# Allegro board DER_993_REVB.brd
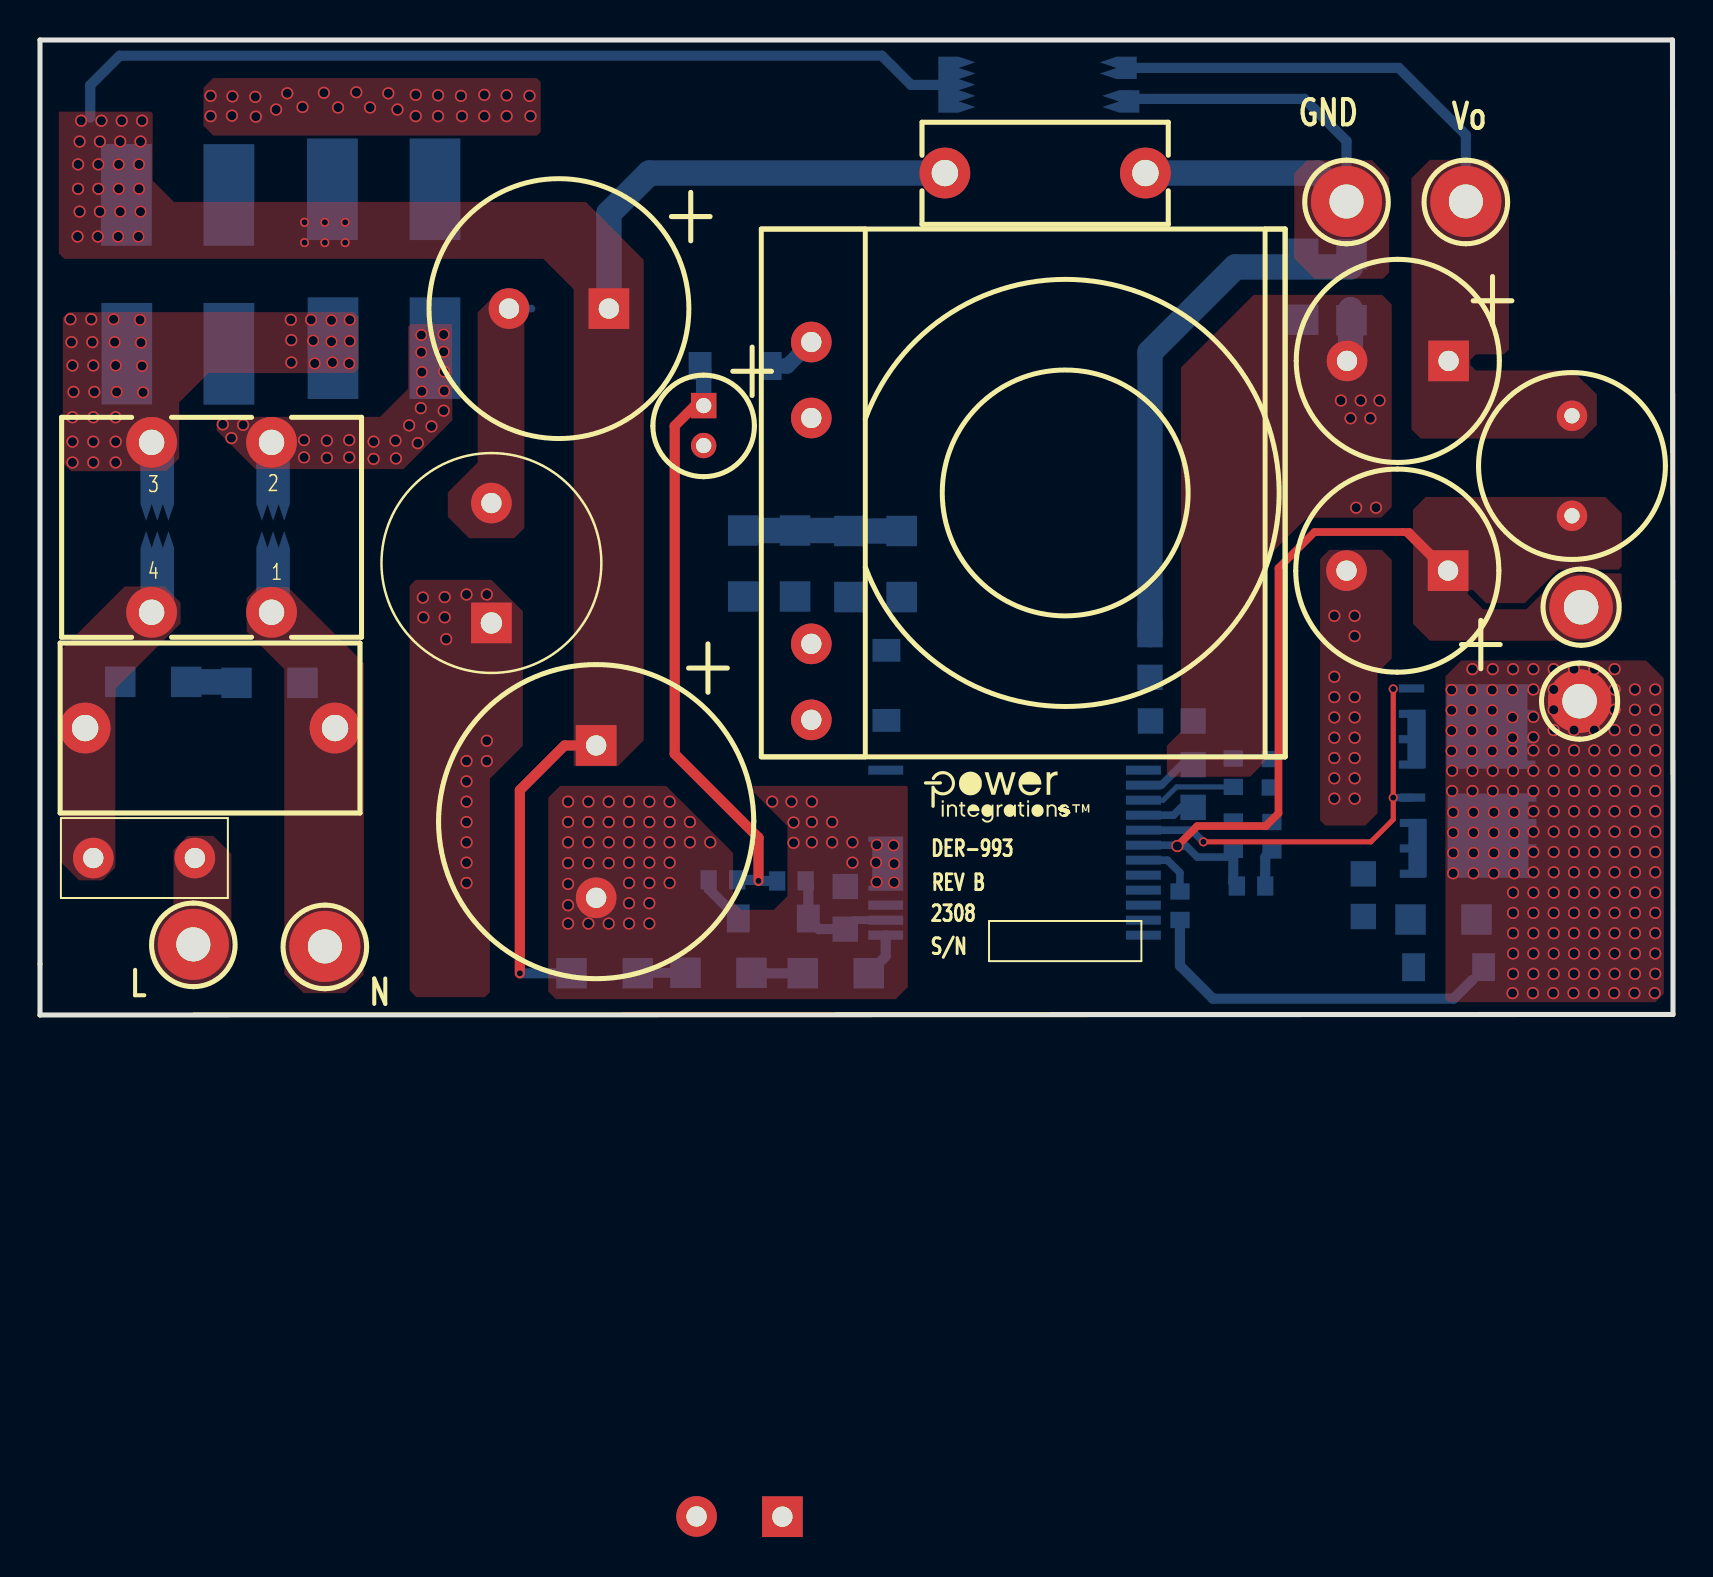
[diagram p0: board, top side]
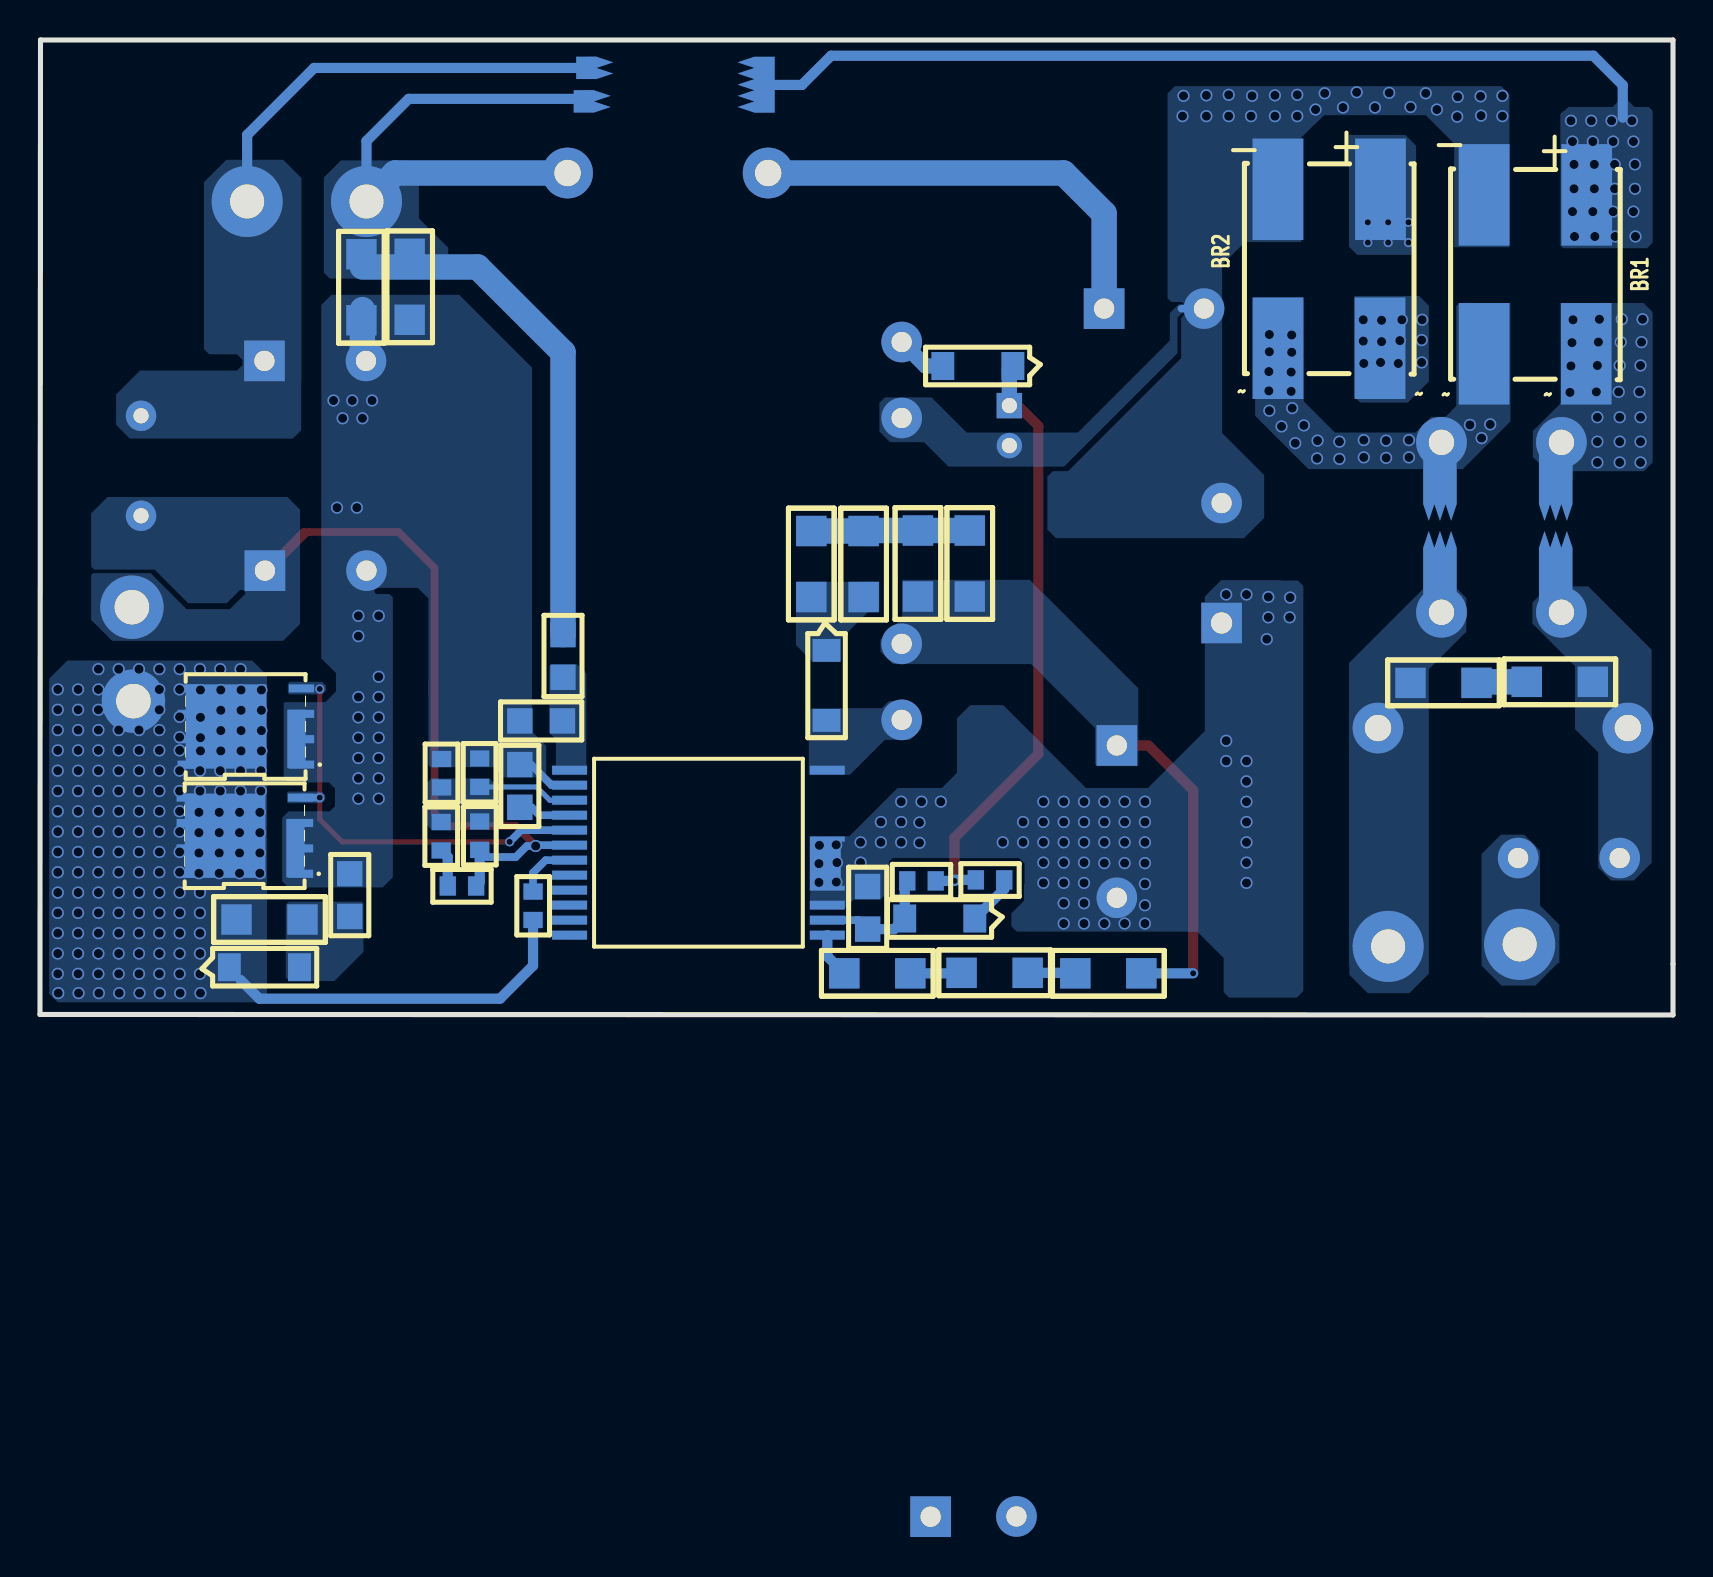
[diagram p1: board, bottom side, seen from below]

Outline 81.69 x 48.77 mm; copper layers: TOP, BOTTOM. Coordinates in mm from the lower left corner of the outline.
Outline path: 0,48.77 81.66,48.77 81.69,0.03 0,0 0,48.77

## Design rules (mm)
constraint set DEFAULT: min track width 0.203

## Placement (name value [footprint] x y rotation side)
BR1  Z4DGP408L-HF  [PI_SM_D_Z4D]  4.34 41.07 180 bottom
BR2  Z4DGP408L-HF  [PI_SM_D_Z4D]  14.66 41.35 180 bottom
C1  68 uF  [PIPOLCAPCLYD13MMD040]  25.96 35.33 180 top
C2  82 uF  [PIPOLCAPCLYD630LS300040]  27.82 13.48 270 top
C4  1 nF  [PISMC1206]  37.77 20.93 90 bottom
C5  22  uF  [PIPOLCAPCLYD200LS80030]  33.2 30.48 270 top
C6  4.7 uF  [PISMC0805]  40.28 4.29 90 bottom
C7  1.5 nF  [PISMC0805]  66.19 7.06 270 bottom
C8  2.2 uF  [PISMC0805]  57.68 12.52 270 bottom
C9  330 pF  [PISMC0603]  59.69 12.83 270 bottom
C10  4.7 uF  [PISMC0805]  57.68 14.71 180 bottom
C11  2.2 nF  [PISMC0603]  61.62 8.23 90 bottom
C12  820 uF  [PIPOLCAPCYLD400LS200040]  70.43 22.23 180 top
C13  820 uF  [PIPOLCAPCYLD400LS200040]  70.46 32.72 180 top
CX1  330 nF  [PINP_XCAPRAD15X8P5X14HD040]  14.76 14.35 180 top
CY1  2.2 nF  [PI_NP475X200LS395D040]  45.26 42.11 0 top
D1  S1MLHRVG  [PI_SM_SOD-123_12]  42.34 18.24 270 bottom
D2  S1MLHRVG  [PI_SM_SOD-123_12]  33.02 32.46 0 bottom
D3  UFM13PL-TP  [PI_SM_SOD-123_12]  72.21 2.39 180 bottom
F1  3.15 A  [PI_RST_MICROFUSE]  7.75 7.85 180 top
FL1  Hole_70mils  [PI_HOLE_70MIL]  77.09 20.37 0 top
FL2  Hole_70mils  [PI_HOLE_70MIL]  77.01 15.67 0 top
L1  18mH  [PI_CMC_18MH_SUMIDASF]  11.58 20.14 180 top
L2  12 uH  [PI_CHOKE_COILCRAFT_RFB1010]  22.58 22.61 90 top
L3  1 uH  [PI_CHOKE_D354LS197D030]  76.63 24.97 90 top
NOREF  -  []  89.79 -219.94 0 top
NOREF#2  -  []  43.66 12.09 0 top
NOREF#3  -  []  0.03 0.03 90 top
NOREF#4  -  []  -329.18 -232.92 0 top
NOREF#5  -  []  0 48.77 0 top
Q3  SIR170DP  [PISMPQFN5X6B]  68.66 7.06 90 bottom
Q4  SIR170DP  [PISMPQFN5X6B]  68.61 12.52 90 bottom
R1  2 M  [PISMR1206]  7.32 16.66 180 bottom
R2  2 M  [PISMR1206]  13.13 16.61 180 bottom
R3  470 k  [PISMR1206]  35.18 20.93 90 bottom
R4  20  [PISMR1206]  40.49 20.9 90 bottom
R5  20  [PISMR1206]  43.1 20.9 90 bottom
R6  11 k  [PISMR0603]  36.88 6.71 0 bottom
R7  100  [PISMR0603]  34.87 6.76 180 bottom
R8  47  [PISMR0603]  57.02 4.75 90 bottom
R9  10  [PISMR1206]  68.55 4.78 0 bottom
R13  0.011  [PISMR1206]  65.61 34.75 90 bottom
R14  10  [PISMR0805]  55.52 19.02 270 bottom
R15  100 k  [PISMR0603]  59.69 8.25 90 bottom
R16  3.92 k  [PISMR0603]  59.87 6.45 0 bottom
R17  11.8 k  [PISMR0603]  61.59 12.8 270 bottom
R18  1.00 M  [PISMR1206]  38.15 2.08 0 bottom
R19  1.20 M  [PISMR1206]  32.28 2.11 0 bottom
R20  1.20 M  [PISMR1206]  26.59 2.08 0 bottom
R21  0.011  [PISMR1206]  63.2 34.77 90 bottom
T1  PQ-2628  [PI_BOBBIN_PQ-2628_6P]  51.28 26.11 0 top
TP1  Line  [PITPKEYSTONE125X125]  7.67 3.53 0 top
TP2  Neutral  [PITPKEYSTONE125X125]  14.25 3.43 0 top
TP3  RED  [PITPKEYSTONE125X125]  71.32 40.69 0 top
TP4  BLK  [PITPKEYSTONE125X125]  65.35 40.69 0 top
U1  INN4275C-Hxxx  [PI_IC_INSOP_24D_IPC]  55.19 12.24 180 bottom
ZD1  MMSZ5247BT1G  [PI_SM_SOD-123_12]  34.92 4.83 0 bottom

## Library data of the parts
BR1 BR2 = DISCRETE BRIDGE_+~~-
C1 = CAP POL: alternate symbols: (pipolcapclyd13x30mmd040H)
C2 = CAP POL: alternate symbols: (pi_polcap_630ls300d40x1319_h)
C4 C6 C7 C10 C11 CY1 = CAP NP
C5 = CAP POL: alternate symbols: (pipolcapclyd200ls80030h)
C8 = CAP NP_0
C9 = CAP NP: alternate symbols: (pismc0603_1)
C12 C13 = CAP POL
CX1 = CAP NP: alternate symbols: (pinp_xcaprad15x8p5x14Hd040H)
D1-D3 = DIODE
F1 = FUSE: alternate symbols: (pirstmicrofusehoz)
FL1 FL2 = FlyingLead
L1 = TORRID 4P_12_43a: alternate symbols: (pi_CMC_18mH_SumidaW,pi_CMC_18mH_Sumida_H,pi_CMC_18mH_SumidaSF)
L2 L3 = INDUCTOR
Q3 Q4 = FET_N_SGD_123_4_5678
R1-R9 R13-R21 = R
T1 = BPQ26/28_6P
TP1-TP4 = TESTPOINT
U1 = INNO4-QR_2: alternate symbols: (pi_ic_insop_24d)
ZD1 = DIODE_ZENER

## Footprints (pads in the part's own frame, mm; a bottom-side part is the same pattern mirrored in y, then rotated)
PI_BOBBIN_PQ-2628_6P
  rect 2.032x2.032 hole 1.016: 1(-14.148,-51.209)
  round 2.032 hole 1.016: 2(-12.7,7.549) 3(-12.7,3.749) 4(-18.44,-51.196) 5(-12.7,-7.549) 6(-12.7,-11.351)
PI_CHOKE_COILCRAFT_RFB1010
  rect 2.032x2.032 hole 1.067: 1(-3,0)
  round 2.032 hole 1.016: 2(3,0)
PI_CHOKE_D354LS197D030
  round 1.524 hole 0.762: 1(0,0) 2(5.001,0)
PI_CMC_18MH_SUMIDASF
  round 2.54 hole 1.27: 1(0,0) 2(0,-8.499) 3(5.999,-8.499) 4(5.999,0)
PI_HOLE_70MIL
  round 3.175 hole 1.727: 1(0,0.025)
PI_IC_INSOP_24D_IPC
  rect 1.75x0.45 smd: 1(0,0) 2(0,-0.749) 3(0,-1.501) 4(0,-2.25) 5(0,-3) 6(0,-3.749) 7(0,-4.501) 8(0,-5.25) 9(0,-5.999) 10(0,-6.749) 11(0,-7.501) 12(0,-8.25) 13(12.89,-8.25) 14(12.89,-7.501) 15(12.89,-6.749) 24(12.89,0)
  custom 0.437x0.437 smd: 16(12.89,-4.671)
PI_NP475X200LS395D040
  round 2.54 hole 1.321: 1(0,0) 2(10.033,0)
PI_RST_MICROFUSE
  round 2.032 hole 1.016: 1(0,0) 2(5.08,0)
PI_SM_D_Z4D
  rect 2.54x5.08 smd: 1(0.025,-0.051) 2(0,-8.001) 3(-5.105,-8.001) 4(-5.105,-0.051)
PI_SM_SOD-123_12
  rect 1.143x1.397 smd: 1(0,0) 2(3.505,0)
PINP_XCAPRAD15X8P5X14HD040
  round 2.54 hole 1.321: 1(0,0) 2(12.499,0)
PIPOLCAPCLYD13MMD040
  rect 2.032x2.032 hole 1.016: 1(-2.499,0)
  round 2.032 hole 1.016: 2(2.499,0)
PIPOLCAPCLYD200LS80030
  rect 1.27x1.27 hole 0.762: 1(0,0)
  round 1.27 hole 0.762: 2(1.999,0)
PIPOLCAPCLYD630LS300040
  rect 2.032x2.032 hole 1.016: 1(0,0)
  round 2.032 hole 1.016: 2(7.62,0)
PIPOLCAPCYLD400LS200040
  rect 2.032x2.032 hole 1.016: 1(0,0)
  round 2.032 hole 1.016: 2(5.08,0)
PISMC0603
  rect 0.813x0.965 smd: 1(0,0) 2(1.422,0)
PISMC0805
  rect 1.27x1.27 smd: 1(0,0) 2(2.134,0)
PISMC1206
  rect 1.524x1.524 smd: 1(0,0) 2(3.302,0)
PISMPQFN5X6B
  rect 0.406x1.27 smd: 1(0,0) 2(1.27,0) 3(2.54,0) 4(3.81,0)
  rect 0.406x1.219 smd: 5(3.81,5.588) 6(2.54,5.588) 7(1.27,5.588) 8(0,5.588)
PISMR0603
  rect 0.813x0.965 smd: 1(0,0) 2(1.422,0)
PISMR0805
  rect 1.27x1.27 smd: 1(0,0) 2(2.134,0)
PISMR1206
  rect 1.524x1.524 smd: 1(0,0) 2(3.302,0)
PITPKEYSTONE125X125
  round 3.556 hole 1.702: 1(0,0)

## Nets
GND: C7.1 C8.1 C9.1 C10.1 C12.2 C13.2 Q3.1 Q3.2 Q3.3(S3) Q4.1 Q4.2 Q4.3(S3) R13.1 R17.1 R21.1 U1.2
P_GND: C2.2 C6.2 L2.1 U1.15 U1.16
S_GND: CY1.2 R13.2 R14.1 R21.2 TP4.1
N12325015: BR1.1 BR2.1 C1.1 C2.1 C4.1 CY1.1 R3.1 R20.1 T1.5
N12325093: C12.1 FL1.1 L3.1 R15.1 R16.1 U1.6
N12325489: C4.2 R3.2 R4.2 R5.2
N12325517: BR1.4 BR2.4 C1.2 C5.2 L2.2 T1.3
N12325687: BR1.3(AC2) BR2.3(AC2) L1.2
N12325801: D1.1 R4.1 R5.1
N12325821: D1.2 T1.6 U1.24
N12326035: D3.1 FL2.1 Q3.5 Q3.6 Q3.7 Q3.8 Q4.5 Q4.6 Q4.7 Q4.8 R8.1 R9.2
N12326051: C7.2 D3.2 R9.1
N12326085: CX1.2 F1.2 L1.4 R1.2
N12326093: CX1.1 L1.1 R2.1 TP2.1
N12326287: C5.1 D2.1 R6.1 R7.1
N12326295: D2.2 T1.2
N12327127: R7.2 ZD1.1
N12327311: C6.1 R6.2 U1.14 ZD1.2
N12329088: BR1.2 BR2.2 L1.3
N12329856: R1.1 R2.2
N12338757: Q3.4 Q4.4 U1.5
N13195866: C8.2 U1.4
N13196457: R8.2 U1.7
N13197196: C13.1 L3.2 TP3.1
N13197416: C10.2 R14.2 U1.1
N13198214: C9.2 C11.2 R15.2 R17.2 U1.3
N13200000: C11.1 R16.2
N13218676: F1.1 TP1.1
N13220742: R18.2 U1.13
N13220770: R18.1 R19.2
N13221160: R19.1 R20.2

Pads without a net: T1 1 4; U1 8 9 10 11 12

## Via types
v1: diameter 0.61, hole 0.457, TOP to BOTTOM, 372 vias
v2: diameter 0.457, hole 0.305, TOP to BOTTOM, 11 vias

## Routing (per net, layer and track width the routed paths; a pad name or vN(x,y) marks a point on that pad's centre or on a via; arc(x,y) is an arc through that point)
GND: length 5.5
  BOTTOM w0.381: C8.1 57.12,12.52 56.09,11.49 U1.2
  BOTTOM w1.27: 65.56,32.66 65.56,35.28
  vias: v1(64.74,19.96) v1(64.74,16.92) v1(64.74,15.9) v1(64.74,14.88) v1(64.74,13.87) v1(64.74,12.85) v1(64.74,11.84) v1(64.74,10.82) v1(65.07,30.73) v1(65.56,29.85) v1(65.76,19.96) v1(65.76,18.95) v1(65.76,15.9) v1(65.76,14.88) v1(65.76,13.87) v1(65.76,12.85) v1(65.76,11.84) v1(65.76,10.82) v1(65.84,25.37) v1(66.07,30.73) v1(66.55,29.85) v1(66.83,25.37) v1(67.01,30.73)
P_GND: length 0.7
  BOTTOM w0.381: 42.3,6.9 U1.16
  vias: v1(19.15,20.88) v1(19.18,19.89) v1(20.24,20.9) v1(20.24,19.89) v1(20.32,18.8) v1(21.34,21.03) v1(21.34,12.7) v1(21.34,11.68) v1(21.34,10.67) v1(21.34,9.65) v1(21.34,8.64) v1(21.34,7.62) v1(21.34,6.6) v1(22.35,21.03) v1(22.35,13.72) v1(22.35,12.7) v1(26.42,10.67) v1(26.42,9.65) v1(26.42,8.64) v1(26.42,7.59) v1(26.42,6.55) v1(26.42,5.49) v1(26.42,4.57) v1(27.43,10.67) v1(27.43,9.65) v1(27.43,8.64) v1(27.43,7.59) v1(27.43,4.57) v1(28.45,10.67) v1(28.45,9.65) v1(28.45,8.64) v1(28.45,7.59) v1(28.45,4.57) v1(29.46,10.67) v1(29.46,9.65) v1(29.46,8.64) v1(29.46,7.62) v1(29.46,6.6) v1(29.46,5.59) v1(29.46,4.57) v1(30.48,10.67) v1(30.48,9.65) v1(30.48,8.64) v1(30.48,7.62) v1(30.48,6.6) v1(30.48,5.59) v1(30.48,4.57) v1(31.5,10.67) v1(31.5,9.65) v1(31.5,8.64) v1(31.5,7.62) v1(31.5,6.6) v1(32.51,9.65) v1(32.51,8.64) v1(33.53,8.64) v1(36.63,10.67) v1(37.59,10.67) v1(37.69,9.63) v1(37.69,8.61) v1(38.61,10.67) v1(38.61,9.65) v1(38.61,8.64) v1(39.62,9.65) v1(39.62,8.64) v1(40.64,8.64) v1(40.64,7.62) v1(41.86,8.51) v1(41.82,7.62) v1(41.85,6.65) v1(42.7,8.48) v1(42.72,7.57) v1(42.72,6.63)
S_GND: length 51
  BOTTOM w0.508: 54.81,45.82 63.25,45.82 65.35,43.71 TP4.1
  BOTTOM w1.27: 65.56,37.41 59.79,37.41 55.52,33.14 R14.1 ; TP4.1 63.93,42.11 CY1.2
N12325015: length 84.5
  TOP w0.508: v2(24,2.08) 24,11.24 26.24,13.48 C2.1
  BOTTOM w0.508: R20.1 v2(24,2.08) ; 2.51,44.88 2.51,46.51 3.99,47.98 42.11,47.98 43.57,46.52 45.28,46.52 45.29,46.53
  BOTTOM w1.27: CY1.1 30.48,42.11 28.46,40.09 C1.1
  vias: v1(1.91,42.54) v1(1.91,41.33) v1(1.88,38.94) v1(2.06,44.73) v1(1.98,43.69) v1(1.98,40.18) v1(2.92,42.54) v1(2.92,41.33) v1(2.9,38.94) v1(3.07,44.73) v1(3,43.69) v1(3,40.18) v1(3.94,42.54) v1(3.94,41.33) v1(3.91,38.94) v1(4.01,43.69) v1(4.01,40.18) v1(4.09,44.73) v1(4.95,42.54) v1(4.95,41.33) v1(4.93,38.94) v1(5.03,43.69) v1(5.03,40.18) v1(5.11,44.73) v2(13.23,39.65) v2(13.23,38.63) v2(14.25,39.65) v2(14.25,38.63) v2(15.27,39.65) v2(15.27,38.63)
N12325093: length 37.8
  TOP w0.203: 68.2,24.16 70.13,22.23 C12.1
  TOP w0.381: C12.1 68.5,24.16 63.75,24.16 61.95,22.35 61.95,10.08 61.32,9.45 57.89,9.45 v1(56.89,8.45)
  BOTTOM w0.381: R15.1 59.33,7.9 57.89,7.9 57.34,8.45 v1(56.89,8.45) 56.85,8.49 U1.6
  BOTTOM w0.508: R15.1 59.69,6.63 R16.1
N12325489: length 7.9
  BOTTOM w1.27: R5.2 R4.2 40.46,24.23 C4.2 R3.2
N12325517: length 1.1
  BOTTOM w0.381: 24.59,35.33 C1.2
  vias: v1(8.53,45.97) v1(8.53,44.96) v1(9.63,45.95) v1(9.6,44.98) v1(10.77,45.92) v1(10.79,44.93) v1(11.81,45.29) v1(12.37,46.1) v1(13.13,45.42) v1(14.2,46.13) v1(14.91,45.39) v1(15.82,46.15) v1(16.51,45.39) v1(17.42,46.1) v1(17.88,45.29) v1(18.8,46.02) v1(18.8,44.96) v1(19.91,46) v1(19.91,44.96) v1(21.06,45.97) v1(21.11,44.96) v1(22.23,46.02) v1(22.23,44.96) v1(23.34,46) v1(23.34,44.96) v1(24.49,45.97) v1(24.54,44.96)
N12325687:
  vias: v1(9.14,29.54) v1(9.58,28.85) v1(10.16,29.51) v1(13.21,28.75) v1(13.21,27.89) v1(14.35,28.73) v1(14.35,27.86) v1(15.47,28.75) v1(15.47,27.89) v1(16.69,28.68) v1(16.69,27.81) v1(17.78,28.73) v1(17.81,27.84) v1(18.47,29.49) v1(18.9,28.6) v1(19.05,30.35) v1(19.08,34.01) v1(19.08,33.15) v1(19.1,32.16) v1(19.1,31.19) v1(19.58,29.44) v1(20.19,34.04) v1(20.19,33.17) v1(20.22,32.18) v1(20.22,31.22) v1(20.19,30.23)
N12326035: length 18
  BOTTOM w0.508: R8.1 57.02,2.46 58.67,0.81 70.71,0.81 71.65,1.75
  vias: v1(70.61,16.26) v1(70.61,15.24) v1(70.61,14.22) v1(70.61,13.21) v1(70.64,12.22) v1(70.64,11.2) v1(70.69,10.13) v1(70.69,9.12) v1(70.69,8.1) v1(70.69,7.09) v1(71.65,17.3) v1(71.63,16.26) v1(71.63,15.24) v1(71.63,14.22) v1(71.63,13.21) v1(71.65,12.22) v1(71.65,11.2) v1(71.7,10.13) v1(71.7,9.12) v1(71.7,8.1) v1(71.7,7.09) v1(72.67,17.3) v1(72.64,16.26) v1(72.64,15.24) v1(72.64,14.22) v1(72.64,13.21) v1(72.67,12.22) v1(72.67,11.2) v1(72.72,10.13) v1(72.72,9.12) v1(72.72,8.1) v1(72.72,7.09) v1(73.66,16.26) v1(73.66,14.88) v1(73.66,13.87) v1(73.66,13.21) v1(73.66,1.09) v1(73.69,17.3) v1(73.69,12.22) v1(73.69,11.2) v1(73.74,10.13) v1(73.74,9.12) v1(73.74,8.1) v1(73.74,7.09) v1(73.69,6.12) v1(73.69,5.11) v1(73.69,4.09) v1(73.69,3.07) v1(73.69,2.06) v1(74.7,17.3) v1(74.7,16.28) v1(74.7,14.91) v1(74.7,13.89) v1(74.7,13.23) v1(74.7,12.22) v1(74.7,11.2) v1(74.7,10.19) v1(74.7,9.17) v1(74.7,8.15) v1(74.7,7.14) v1(74.7,6.12) v1(74.7,5.11) v1(74.7,4.09) v1(74.7,3.07) v1(74.7,2.06) v1(74.68,1.09) v1(75.72,17.3) v1(75.72,16.28) v1(75.72,15.27) v1(75.72,14.25) v1(75.72,13.23) v1(75.72,12.22) v1(75.72,11.2) v1(75.72,10.19) v1(75.72,9.17) v1(75.72,8.15) v1(75.72,7.14) v1(75.72,6.12) v1(75.72,5.11) v1(75.72,4.09) v1(75.72,3.07) v1(75.72,2.06) v1(75.69,1.09) v1(76.73,17.3) v1(76.73,14.25) v1(76.73,13.23) v1(76.73,12.22) v1(76.73,11.2) v1(76.73,10.19) v1(76.73,9.17) v1(76.73,8.15) v1(76.73,7.14) v1(76.73,6.12) v1(76.73,5.11) v1(76.73,4.09) v1(76.73,3.07) v1(76.73,2.06) v1(76.71,1.09) v1(77.75,17.3) v1(77.75,14.25) v1(77.75,13.23) v1(77.75,12.22) v1(77.75,11.2) v1(77.75,10.19) v1(77.75,9.17) v1(77.75,8.15) v1(77.75,7.14) v1(77.75,6.12) v1(77.75,5.11) v1(77.75,4.09) v1(77.75,3.07) v1(77.75,2.06) v1(77.72,1.09) v1(78.77,17.3) v1(78.77,16.28) v1(78.77,15.27) v1(78.77,14.25) v1(78.77,13.23) v1(78.77,12.22) v1(78.77,11.2) v1(78.77,10.19) v1(78.77,9.17) v1(78.77,8.15) v1(78.77,7.14) v1(78.77,6.12) v1(78.77,5.11) v1(78.77,4.09) v1(78.77,3.07) v1(78.77,2.06) v1(78.74,1.09) v1(79.76,1.09) v1(79.78,16.28) v1(79.78,15.27) v1(79.78,14.25) v1(79.78,13.23) v1(79.78,12.22) v1(79.78,11.2) v1(79.78,10.19) v1(79.78,9.17) v1(79.78,8.15) v1(79.78,7.14) v1(79.78,6.12) v1(79.78,5.11) v1(79.78,4.09) v1(79.78,3.07) v1(79.78,2.06) v1(80.77,1.09) v1(80.8,16.28) v1(80.8,15.27) v1(80.8,14.25) v1(80.8,13.23) v1(80.8,12.22) v1(80.8,11.2) v1(80.8,10.19) v1(80.8,9.17) v1(80.8,8.15) v1(80.8,7.14) v1(80.8,6.12) v1(80.8,5.11) v1(80.8,4.09) v1(80.8,3.07) v1(80.8,2.06)
N12326287: length 30.4
  TOP w0.508: C5.1 32.77,30.48 31.75,29.46 31.75,13.06 35.94,8.86 v2(35.94,6.71)
  BOTTOM w0.508: R6.1 v2(35.94,6.71) 35.89,6.76 R7.1
  BOTTOM w0.762: C5.1 33.2,32.28 D2.1
N12326295: length 2.6
  BOTTOM w0.762: T1.2 37.38,32.46 D2.2
N12327127: length 2.5
  BOTTOM w0.508: R7.2 33.45,6.3 ZD1.1
N12327311: length 6.2
  BOTTOM w0.381: U1.14 40.73,4.74 C6.1
  BOTTOM w0.508: R6.2 38.43,6.58 ZD1.2 38.96,4.29 C6.1
N12329088:
  vias: v1(1.52,34.8) v1(1.57,33.66) v1(1.63,32.49) v1(1.63,29.9) v1(1.63,28.68) v1(1.63,27.64) v1(1.68,31.17) v1(2.57,34.8) v1(2.62,33.66) v1(2.67,32.49) v1(2.67,29.9) v1(2.67,28.68) v1(2.67,27.64) v1(2.72,31.17) v1(3.68,34.8) v1(3.73,33.66) v1(3.78,32.49) v1(3.84,31.17) v1(3.78,29.9) v1(3.78,28.68) v1(3.78,27.64) v1(5,34.77) v1(5.05,33.63) v1(5.11,32.46) v1(5.16,31.14) v1(12.55,34.77) v1(12.57,33.76) v1(12.57,32.64) v1(13.56,34.77) v1(13.67,33.73) v1(13.74,32.59) v1(14.58,34.75) v1(14.58,33.68) v1(14.63,32.64) v1(15.47,32.59) v1(15.49,34.77) v1(15.49,33.71)
N12329856: length 2.5
  BOTTOM w1.27: R1.1 9.78,16.66 R2.2
N12338757: length 20.7
  TOP w0.254: v2(67.69,16.31) v2(67.69,10.87) 67.69,9.78 66.57,8.66 v2(58.19,8.66)
  BOTTOM w0.381: v2(58.19,8.66) 57.61,9.24 U1.5 ; Q3.4 v2(67.69,10.87)
N13195866: length 2.7
  BOTTOM w0.381: U1.4 56.7,9.99 57.1,10.39 C8.2
N13196457: length 3
  BOTTOM w0.381: U1.7 56.4,7.74 57.02,7.11 R8.2
N13197196: length 21.6
  BOTTOM w0.508: 54.41,47.35 54.43,47.37 67.97,47.37 71.32,44.02 TP3.1
N13198214: length 4.8
  BOTTOM w0.254: C9.2 56.85,11.4 56.18,10.74 U1.3
N13200000: length 1.9
  BOTTOM w0.508: R16.2 61.29,7.9 C11.1
N13220742: length 2.3
  BOTTOM w0.508: U1.13 42.3,2.93 R18.2
N13220770: length 2.6
  BOTTOM w0.508: R18.1 35.61,2.08 R19.2
N13221160: length 2.4
  BOTTOM w0.508: R19.1 29.92,2.11 R20.2

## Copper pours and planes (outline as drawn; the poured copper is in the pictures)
GND on BOTTOM (solid shape): 69.32,12.34 68.4,12.34 68.4,15.27 69.32,15.27
GND on BOTTOM (solid shape): 69.37,6.88 68.45,6.88 68.45,9.8 69.37,9.8
GND on TOP: 64.49,23.27 67.11,23.27 67.61,22.76 67.61,17.83 66.9,17.12 66.9,10.08 66.29,9.47 64.26,9.47 64.26,9.5 64.03,9.73 64.03,22.81
GND on TOP: 63.37,24.87 61.32,22.81 61.32,15.85 61.25,15.79 61.25,12.64 60.53,11.91 56.54,11.91 56.36,12.09 56.36,13.46 57.07,14.17 57.07,32.38 60.71,36.02 67.13,36.02 67.61,35.53 67.61,25.4 67.08,24.87
GND on BOTTOM: 69.44,15.65 69.49,15.6 69.49,11.86 69.37,11.73 69.37,11.71 69.29,11.63 67.23,11.63 66.93,11.33 66.93,10.44 67.18,10.19 69.24,10.19 69.57,9.86 69.57,6.68 69.27,6.38 64.54,6.38 64.03,6.88 64.03,20.88 64.21,21.06 64.87,21.06 64.95,21.13 64.95,21.26 64.85,21.36 62.79,21.36 62.26,20.83 62.26,15.95 61.54,15.24 57.07,15.24 57.07,32.38 60.71,36.02 67.11,36.02 67.61,35.51 67.61,17.83 66.88,17.09 66.88,16.18 67.41,15.65
GND on BOTTOM: 57.05,14.15 57.05,15.27 57.25,15.47 58.39,15.47 59.18,16.26 60.93,16.26 61.62,16.94 62.03,16.94 62.26,16.71 62.26,12.5 62.15,12.4 59,12.4 58.5,11.89 56.36,11.89 56.36,13.46
P_GND on TOP: 26.01,11.46 31.32,11.46 34.67,8.1 34.67,5.87 34.57,5.77 35.08,5.26 36.7,5.26 37.39,5.94 37.39,9.45 35.69,11.15 35.69,11.46 43.36,11.46 43.41,11.4 43.41,1.4 42.8,0.79 25.81,0.79 25.43,1.17 25.43,10.87
P_GND on TOP: 18.8,21.77 22.58,21.77 24.16,20.19 24.16,13.46 22.5,11.81 22.5,1.14 22.25,0.89 18.82,0.89 18.49,1.22 18.49,21.46
P_GND on BOTTOM: 19.61,21.74 22.61,21.74 23.42,20.93 23.42,14.2 26.26,11.35 29.36,11.35 33.5,15.49 35.15,15.49 35.81,14.83 35.81,12.12 36.58,11.35 38.79,11.35 41.2,8.94 43.13,8.94 43.15,8.92 43.15,6.05 43.17,6.03 43.17,5.28 43.15,5.28 43.13,5.26 41.5,5.26 41,5.77 39.65,5.77 39.22,6.2 39.22,7.67 39.04,7.85 32.72,7.85 32.44,7.57 32.44,6.55 32.46,6.53 32.46,5.72 33.07,5.11 33.1,5.11 33.1,4.45 32.82,4.17 23.8,4.17 22.48,2.84 22.48,1.14 22.2,0.86 18.82,0.86 18.49,1.19 18.49,21.46 18.77,21.74 18.78,21.73 19.6,21.73
S_GND on BOTTOM (solid shape): 54.99,46.26 54.99,45.14 53.97,45.14 53.14,45.42 53.97,45.69 53.14,45.97 53.97,46.25 53.95,46.26
S_GND on TOP: 67.49,41.88 67.49,37.13 67.18,36.83 63.75,36.83 62.74,37.85 62.74,42.09 63.4,42.75 66.62,42.75
S_GND on BOTTOM: 67.49,41.88 67.49,37.13 67.18,36.83 61.65,36.83 61.26,37.21 61.26,38.38 62.74,39.85 62.74,42.09 63.4,42.75 66.62,42.75
N12325015 on BOTTOM (solid shape): 46.79,47.65 45.95,47.37 46.79,47.09 45.95,46.81 46.79,46.53 45.95,46.25 46.79,45.97 45.95,45.69 46.79,45.42 45.95,45.14 45.97,45.13 44.93,45.13 44.93,47.93 45.95,47.93
N12325015 on TOP: 0.97,45.19 5.54,45.19 5.64,45.09 5.64,41.73 6.71,40.67 27.3,40.67 30.2,37.77 30.2,13.74 28.91,12.45 26.75,12.45 26.7,12.5 26.7,36.3 25.17,37.82 1.22,37.82 0.94,38.1 0.94,45.16
N12325015 on BOTTOM: 38.53,21.77 32.18,21.77 26.75,16.33 26.75,12.5 26.8,12.45 28.8,12.45 28.91,12.55 28.91,14.35 32.11,17.55 39.01,17.55 39.65,18.19 39.65,18.77 38.56,19.86 38.56,21.74
N12325015 on BOTTOM: 5.64,45.06 5.49,45.21 5.44,45.21 5.23,45.42 3.02,45.42 2.67,45.77 2.29,45.77 1.93,45.42 1.22,45.42 1.02,45.21 1.02,38.63 1.3,38.35 5.51,38.35 5.64,38.48
N12325015 on BOTTOM: 16.21,44.02 13.39,44.02 12.85,43.48 12.85,38.28 13.11,38.02 15.8,38.02 16.21,38.43
N12325093 on TOP, BOTTOM: 69.52,18.72 78.08,18.72 79.12,19.76 79.12,22.02 79.04,22.1 76.15,22.1 74.35,20.29 72.19,20.29 71.42,21.06 71.42,21.16 71.53,21.26 71.68,21.26 72.34,20.6 74.27,20.6 75.95,22.28 78.97,22.28 79.12,22.43 79.12,25.1 78.31,25.91 69.32,25.91 68.68,25.27 68.68,19.56
N12325517 on TOP: 25.04,44.17 25.04,46.66 24.84,46.86 8.66,46.86 8.18,46.38 8.18,44.48 8.66,43.99 24.87,43.99
N12325517 on TOP: 24.23,35.92 24.23,24.36 23.72,23.85 21.46,23.85 20.4,24.92 20.4,26.14 21.89,27.64 21.89,35.14 23.06,36.31 23.84,36.31
N12325517 on BOTTOM: 21.46,23.85 20.45,24.87 20.45,27 22.56,29.11 22.56,37.52 21.41,38.66 18.59,38.66 18.59,43.79 18.64,43.84 17.93,44.55 17.91,44.55 17.45,45.01 12.37,45.01 10.95,43.59 10.95,38.4 8.2,38.4 8.18,38.43 8.18,46.05 8.59,46.46 24.92,46.46 25.29,46.09 25.29,35.85 25.1,35.66 24.56,35.66 24.41,35.51 24.41,35.05 24.6,34.86 24.6,32.85 30.25,27.2 31.01,27.2 31.29,26.92 31.29,24.28 30.86,23.85
N12325517 on BOTTOM: 35.33,29.13 29.77,29.13 25.17,33.73 25.17,35.1 24.74,35.53 24.23,35.53 24.23,35.43 24.79,34.87 24.79,33.1 30.45,27.43 36.25,27.43 37.46,28.65 39.17,28.65 39.7,29.18 39.7,30.61 39.42,30.89 37.08,30.89
N12325687 on BOTTOM (solid shape): 12.5,25.55 12.22,24.71 11.94,25.55 11.66,24.71 11.38,25.55 11.1,24.71 10.82,25.55 10.82,27.91 12.5,27.91
N12325687 on TOP: 17.02,29.92 18.42,31.32 18.42,34.42 18.57,34.57 20.62,34.57 20.62,29.74 18.19,27.3 10.77,27.3 8.84,29.24 8.84,29.69 9.07,29.92
N12325687 on BOTTOM: 18.47,35.86 20.75,35.86 20.9,35.71 20.9,29.97 18.24,27.3 10.52,27.3 8.13,29.69 8.13,35.61 10.69,35.61 10.85,35.46 10.85,30.45 11.38,29.92 12.09,29.92 12.88,29.13 16.92,29.13 18.47,30.68
N12325801 on BOTTOM: 39.7,21.67 43.84,21.67 43.87,21.69 43.87,18.49 43.03,17.65 41.71,17.65 41.61,17.75 41.61,18.82 40.26,20.17 39.73,20.17 39.7,20.19
N12325821 on BOTTOM: 38.2,15.7 39.22,15.7 39.57,15.34 43.08,15.34 43.23,15.19 43.23,12.01 41.17,12.01 39.42,13.77 38.15,13.77 37.62,14.3 37.62,15.11
N12326035 on BOTTOM (solid shape): 74.4,12.32 70.36,12.32 70.36,16.54 74.4,16.54
N12326035 on BOTTOM (solid shape): 74.45,6.86 70.41,6.86 70.41,11.07 74.45,11.07
N12326035 on TOP: 70.46,0.64 70.31,0.79 70.31,16.94 71.09,17.73 80.34,17.73 81.23,16.84 81.23,1.07 80.8,0.64
N12326035 on BOTTOM: 70.69,0.64 70.33,0.99 70.33,16.99 71.07,17.73 80.31,17.73 81.23,16.81 81.23,1.07 80.8,0.64
N12326051 on BOTTOM: 65.58,5.66 69.24,5.66 69.39,5.51 69.39,1.88 69.22,1.7 66.95,1.7 65.51,3.15 65.51,5.59
N12326085 on BOTTOM (solid shape): 6.71,23.37 6.71,19.94 5.03,19.94 5.03,23.37 5.31,24.21 5.59,23.37 5.87,24.21 6.15,23.37 6.43,24.21
N12326085 on TOP: 1.07,7.62 1.07,18.26 4.24,21.44 6.22,21.44 7.04,20.62 7.04,19.58 3.77,16.32 3.77,7.38 3.12,6.73 1.96,6.73
N12326085 on BOTTOM: 1.07,7.62 1.07,18.26 4.24,21.44 6.22,21.44 7.04,20.62 7.04,19.58 4.9,17.45 4.9,14.3 3.75,13.14 3.75,7.38 3.1,6.73 1.96,6.73
N12326093 on BOTTOM (solid shape): 12.5,23.37 12.5,19.53 10.82,19.53 10.82,23.37 11.1,24.21 11.38,23.37 11.66,24.21 11.94,23.37 12.22,24.21
N12326093 on TOP, BOTTOM: 10.9,21.41 12.4,21.41 16.21,17.6 16.21,2.46 16.19,2.45 16.19,2.02 15.27,1.09 13.18,1.09 12.22,2.06 12.22,17.3 10.34,19.18 10.34,20.85
N12329088 on BOTTOM (solid shape): 6.71,25.55 6.43,24.71 6.15,25.55 5.87,24.71 5.59,25.55 5.31,24.71 5.03,25.55 5.03,26.57 5,28.63 6.71,28.63
N12329088 on TOP: 1.14,27.61 1.55,27.2 6.32,27.2 6.96,27.84 6.96,30.63 8.43,32.11 15.7,32.11 15.93,32.33 15.93,34.92 15.7,35.15 1.42,35.15 1.14,34.87
N12329088 on BOTTOM: 12.7,35.97 15.9,35.97 15.95,35.92 15.95,30.94 15.65,30.63 13.26,30.63 12.22,31.67 12.22,35.48
N12329088 on BOTTOM: 5.59,35.61 5.59,30.63 7.01,29.21 7.01,27.91 6.3,27.2 1.45,27.2 1.02,27.64 1.02,35.15 1.47,35.61
N12338757 on BOTTOM: 67.59,11.18 69.27,11.18 69.32,11.13 69.32,10.64 69.27,10.59 67.59,10.59 67.41,10.77 67.41,11
N12338757 on BOTTOM: 67.56,16.66 69.19,16.66 69.29,16.56 69.29,16.1 69.22,16.03 67.54,16.03 67.39,16.18 67.39,16.48
N13197196 on BOTTOM (solid shape): 54.86,47.93 54.86,46.81 53.85,46.81 53.01,47.09 53.85,47.37 53.01,47.65 53.85,47.93 53.83,47.94
N13197196 on TOP: 68.61,41.86 68.61,29.29 69.06,28.83 77.19,28.83 77.88,29.51 77.88,31.04 77.32,31.6 77.29,31.6 76.66,32.23 71.83,32.23 71.55,32.51 71.55,32.77 71.83,33.05 73.23,33.05 73.48,33.3 73.48,41.66 72.36,42.77 69.52,42.77
N13197196 on BOTTOM: 68.61,41.86 68.61,31.72 68.62,31.71 68.62,29.25 69.04,28.83 77.19,28.83 77.88,29.51 77.88,31.04 76.68,32.23 71.83,32.23 71.55,32.51 71.55,32.77 71.83,33.05 73.23,33.05 73.48,33.3 73.48,41.66 72.36,42.77 69.52,42.77
N13197416 on BOTTOM: 56.21,14.12 56.21,17.42 56.08,17.55 54.84,17.55 54.36,17.07 54.36,12.04 55.88,12.04 55.88,13.79
N13198214 on BOTTOM: 59.21,11.84 62.1,11.84 62.33,11.61 62.33,9.5 62.05,9.22 60.48,9.22 60.3,9.4 59,9.4 58.8,9.6 58.8,11.43
N13218676 on TOP: 8.67,8.95 9.58,8.05 9.58,2.46 8.59,1.47 6.88,1.47 5.77,2.59 5.69,2.59 5.69,4.5 6.68,5.49 6.68,8.25 7.38,8.95
N13218676 on BOTTOM: 7.44,9.02 8.61,9.02 9.58,8.05 9.58,2.46 8.59,1.47 6.88,1.47 5.77,2.59 5.69,2.59 5.69,4.52 6.65,5.49 6.65,8.23

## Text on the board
Ref Des/Silkscreen Top: 2308 | S/N | DER-993 | REV B | L | N | GND | Vo
User.5: 11.  TRACE SPACE +/- 0.003" | 13. 2 LAYERS BOARD TOP, BOT. | PLEASE DELETE THESE PINS
User.9: FIGURE | FINISHED_SIZE | 12.0 | 18.0 | 30.0 | 40.0 | 42.0 | 50.0 | 52.0 | 67.0 | 68.0 | DRILL CHART: TOP to BOTTOM | ALL UNITS ARE IN MILS | TOLERANCE_DRILL | +0.0/-0.0 | +3.0/-3.0 | PLATED | QTY | 11 | 372 | 4 | 16 | 1 | 2
